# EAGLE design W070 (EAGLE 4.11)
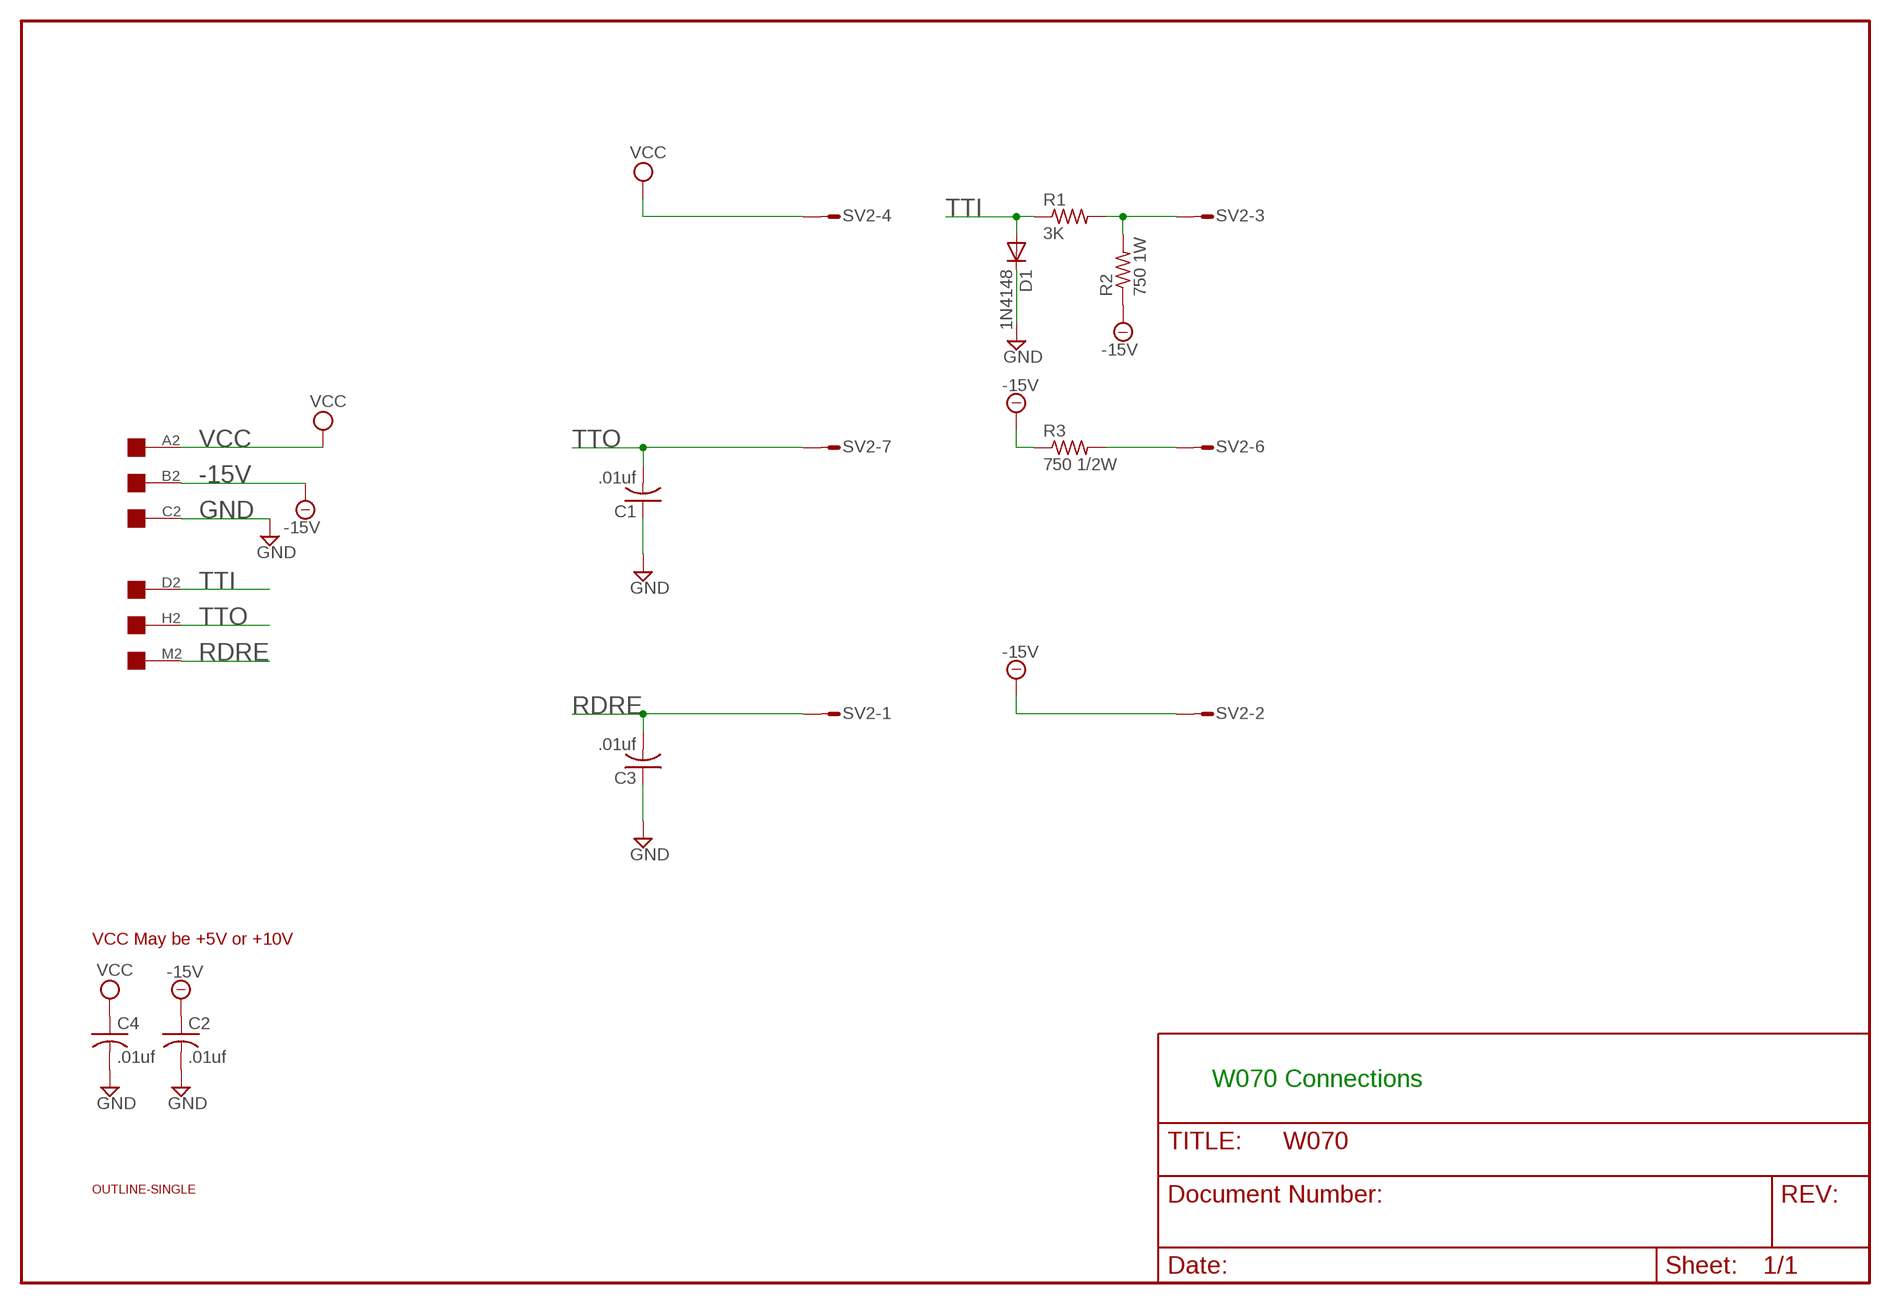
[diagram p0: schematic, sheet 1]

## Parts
C1  .01uf  C-US050-025X075  [C050-025X075]
C2  .01uf  C-US050-025X075  [C050-025X075]
C3  .01uf  C-US050-025X075  [C050-025X075]
C4  .01uf  C-US050-025X075  [C050-025X075]
D1  1N4148  [DO35-10]
EDGE  EDGE-1  [EDGE-CON1]
R1  3K  R-US_0207/10  [0207/10]
R2  750 1W  R-US_0309/12  [0309/12]
R3  750 1/2W  R-US_0309/12  [0309/12]
SV2  L08P  [L08P]
U$1  OUTLINE-SINGLE  [SINGLE]

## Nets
-15V: C2.1 EDGE.B2 R2.1 R3.1 SV2.2
GND: C1.1 C2.2 C3.1 C4.2 D1.C EDGE.C2
N$1: R3.2 SV2.6
N$2: R1.2 R2.2 SV2.3
RDRE: C3.2 EDGE.M2 SV2.1
TTI: D1.A EDGE.D2 R1.1
TTO: C1.2 EDGE.H2 SV2.7
VCC: C4.1 EDGE.A2 SV2.4
Unconnected: EDGE.E2 EDGE.F2 EDGE.J2 EDGE.K2 EDGE.L2 EDGE.N2 EDGE.P2 EDGE.R2 EDGE.S2 EDGE.T2 EDGE.U2 EDGE.V2 SV2.5 SV2.8

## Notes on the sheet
- VCC May be +5V or +10V
- W070 Connections

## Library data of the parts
C1-C4 = rcl:C-US: CAPACITOR, American symbol
D1 = diode:1N4148: DIODE
EDGE = dec-con:EDGE-1: Single-Sided DEC Edge Connector -- (side 2)
R1-R3 = rcl:R-US_: RESISTOR, American symbol
SV2 = con-amp-mt:L08P: AMP MT CONNECTOR
U$1 = dec-con:OUTLINE-*: Board outlines for DEC boards.

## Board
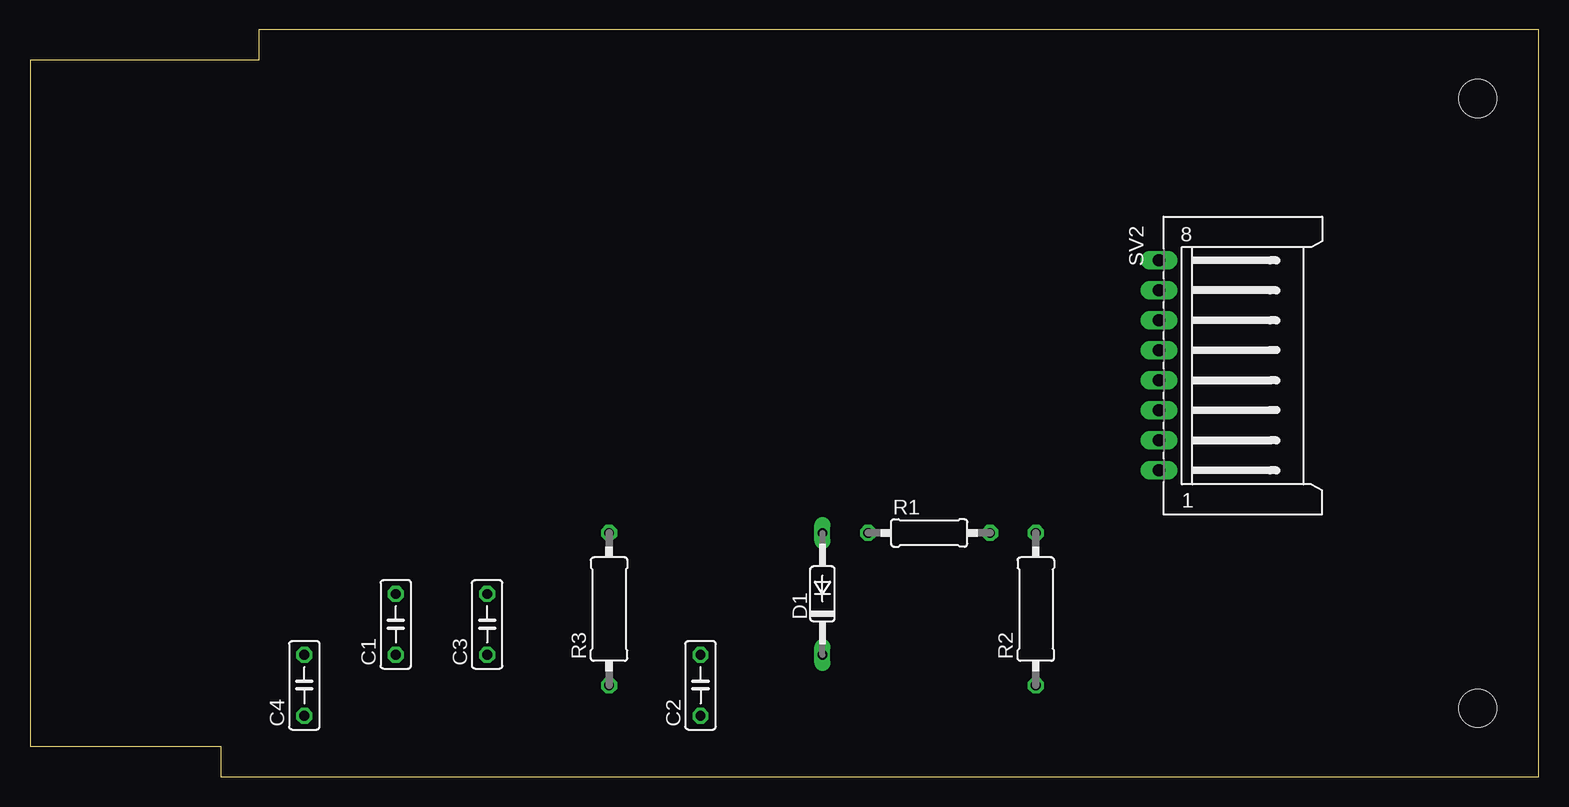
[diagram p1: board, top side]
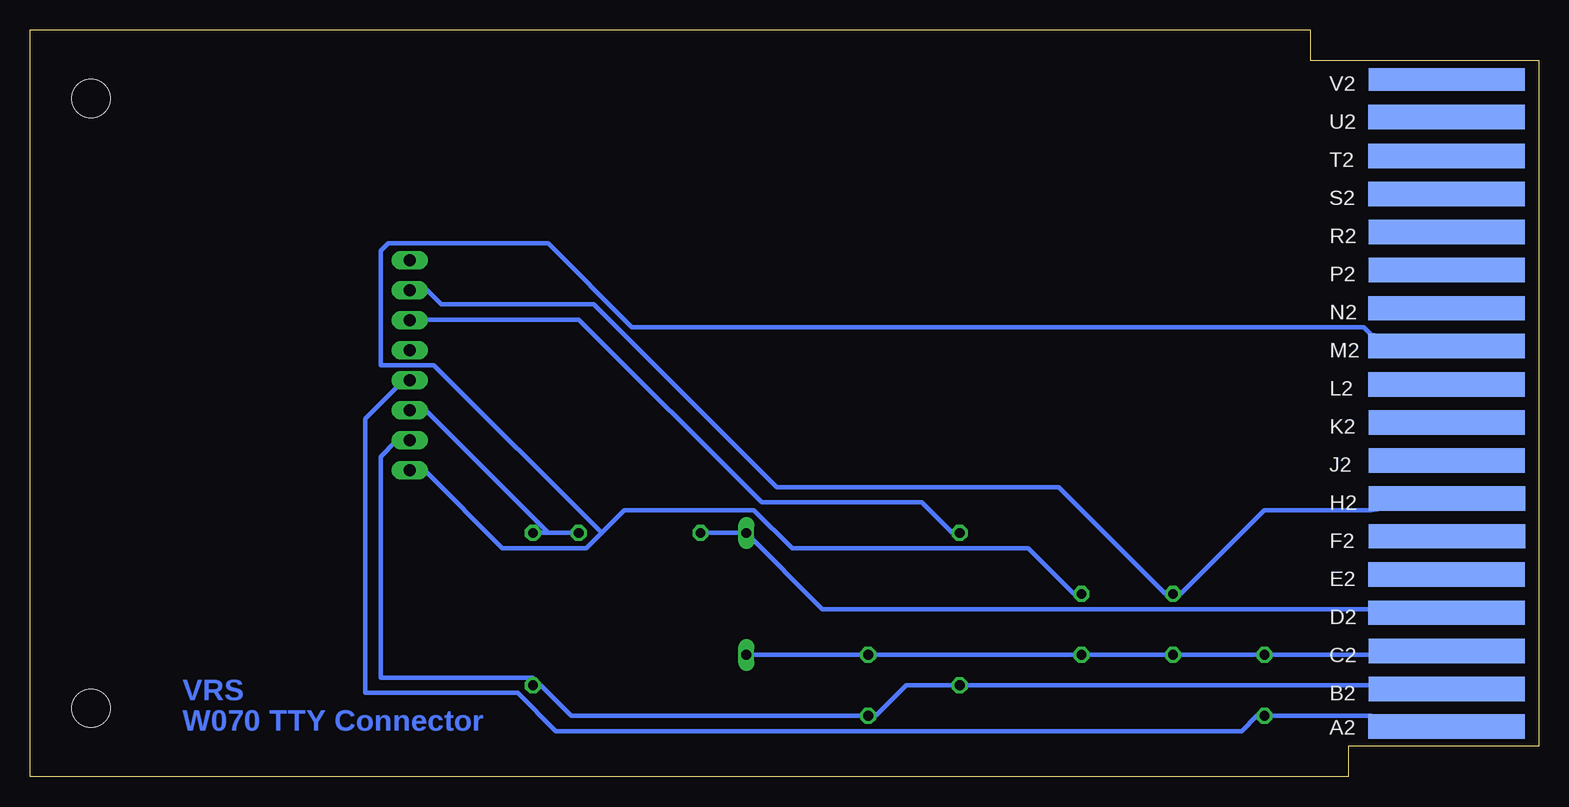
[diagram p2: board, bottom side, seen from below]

Size 125.73 x 62.23 mm. Coordinates in mm from the lower left corner, seen from the top.
Copper layers (1*16): Top 0.035mm / dielectric 1.5mm / Bottom 0.035mm
Design rules "15mils": minimum track width 15mil, minimum drill 24mil, track to track 15mil, track to pad 10mil, pad to pad 10mil, via to via 10mil, smd to smd 10mil, copper to edge 25mil, drill to drill 10mil, minimum pad ring 10mil, minimum via ring 8mil, stop-mask expansion 0mil, vias tented up to drill 0mil, thermal gap 10mil

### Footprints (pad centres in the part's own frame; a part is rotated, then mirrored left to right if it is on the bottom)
C050-025X075 = drill 0.813 octagon: 1 -2.54,0; 2 2.54,0
DO35-10 = drill 0.813 long: A 5.08,0; C -5.08,0
EDGE-CON1 = smd 13.017 x 2.032 bottom: A2 7.69,4.194; B2 7.668,7.328; C2 7.668,10.49; D2 7.693,13.665; E2 7.693,16.84; F2 7.642,20.041; H2 7.642,23.19; J2 7.668,26.34; K2 7.668,29.515; L2 7.693,32.69; M2 7.693,35.89; N2 7.693,39.04; P2 7.668,42.24; R2 7.668,45.39; S2 7.693,48.565; T2 7.693,51.74; U2 7.693,54.966 | smd 13.017 x 1.905 bottom: V2 7.668,58.102
0207/10 = drill 0.813 octagon: 1 -5.08,0; 2 5.08,0
0309/12 = drill 0.813 octagon: 1 -6.35,0; 2 6.35,0
L08P = drill 1.016 long: 1 8.75,-6.25; 2 6.25,-6.25; 3 3.75,-6.25; 4 1.25,-6.25; 5 -1.25,-6.25; 6 -3.75,-6.25; 7 -6.25,-6.25; 8 -8.75,-6.25
SINGLE = hole 3.175: 120.65,56.515; 120.65,5.715

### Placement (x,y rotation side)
C1  30.48,12.7 90 top
C2  55.88,7.62 90 top
C3  38.1,12.7 90 top
C4  22.86,7.62 90 top
D1  66.04,15.24 90 top
EDGE  0,0 0 top
R1  74.93,20.32 0 top
R2  83.82,13.97 90 top
R3  48.26,13.97 90 top
SV2  100.33,34.29 270 top
U$1  0,0 0 top

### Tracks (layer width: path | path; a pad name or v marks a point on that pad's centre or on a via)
-15V
  Bottom 0.381: SV2.2 95.25,27.94 96.52,26.67 96.52,8.26 83.82,8.26 R2.1 83.19,7.62 80.65,5.08 C2.1 55.25,5.08 52.71,7.62 R3.1 13.97,7.62 EDGE.B2
GND
  Bottom 0.381: D1.C C2.2 C3.1 C1.1 C4.2 13.97,10.16 EDGE.C2
N$1
  Bottom 0.381: R3.2 48.9,20.32 51.44,22.86 64.77,22.86 80.01,38.1 92.71,38.1 SV2.6
N$2
  Bottom 0.381: R1.2 82.55,20.32 | 82.55,20.32 R2.2 | 82.55,20.32 92.71,30.48 SV2.3
RDRE
  Bottom 0.381: 78.11,20.32 79.38,19.05 86.36,19.05 92.71,25.4 SV2.1 | 78.11,20.32 76.2,22.23 65.41,22.23 62.23,19.05 42.55,19.05 38.74,15.24 C3.2 | 78.11,20.32 92.08,34.29 96.52,34.29 96.52,43.81 95.89,44.45 82.55,44.45 75.57,37.47 14.61,37.47 13.97,36.83 EDGE.M2
TTI
  Bottom 0.381: R1.1 D1.A 59.69,13.97 13.97,13.97 EDGE.D2
TTO
  Bottom 0.381: EDGE.H2 13.97,22.23 22.86,22.23 29.85,15.24 C1.2 31.12,15.24 40.01,24.13 63.5,24.13 78.74,39.37 91.44,39.37 92.71,40.64 SV2.7
VCC
  Bottom 0.381: EDGE.A2 13.97,5.08 C4.1 23.5,5.08 24.77,3.81 81.92,3.81 85.09,6.99 97.79,6.99 97.79,29.84 95.25,32.38 SV2.4

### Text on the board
Bottom: VRS | W070 TTY Connector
